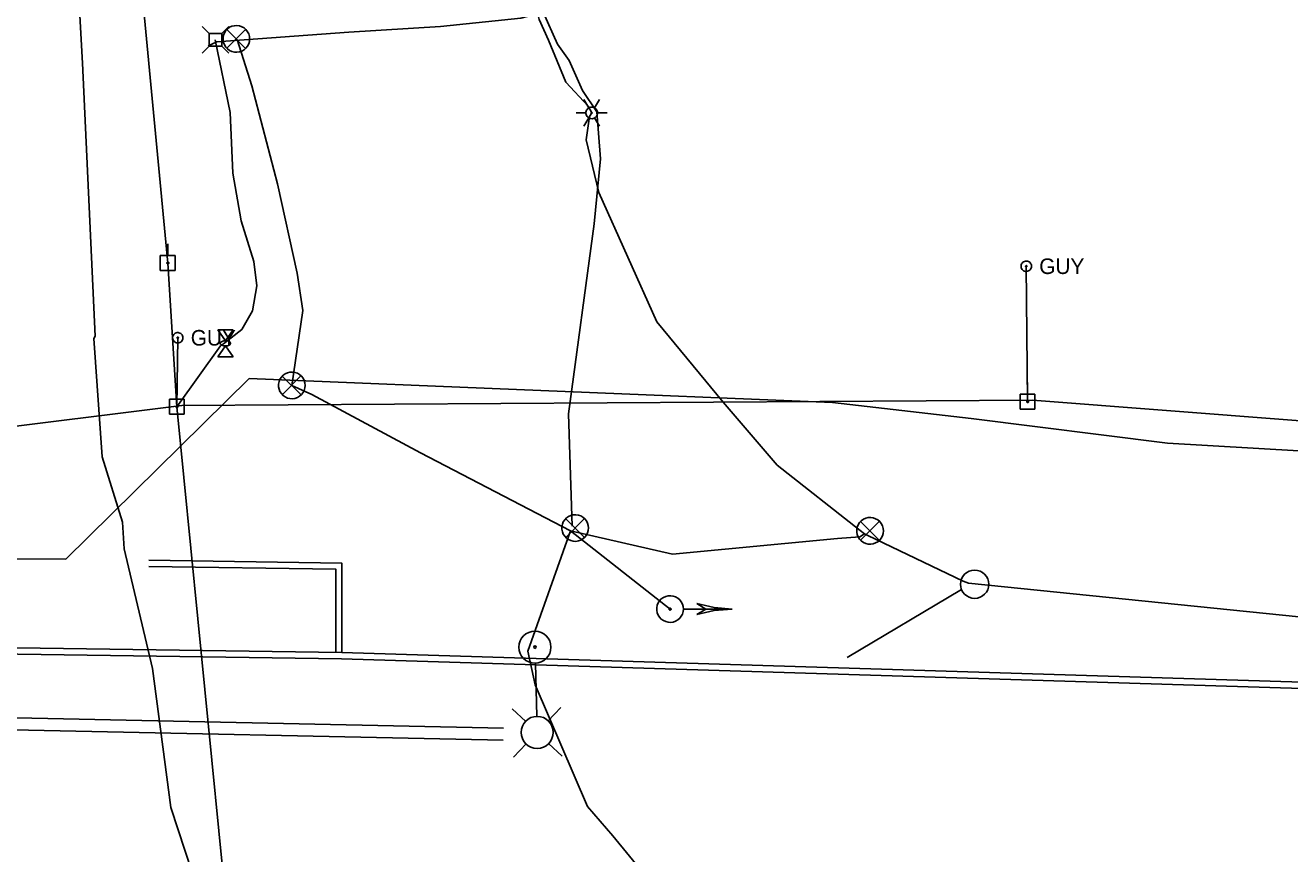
# Model space of a CAD drawing. Extents: x 596028 to 606371, y 330010 to 403088.
# Drawn here: x 603448.5 to 603761.1, y 349941 to 350145.8 of the extents above; entities that cross this region are included whole.
import ezdxf

# ---------------------------------------------------------------- set-up
doc = ezdxf.new("R2010")
doc.units = 0
for name, color, linetype in [('E_FTMS', 7, 'Continuous'), ('E_FTMS_Conduit', 7, 'Continuous'), ('E_LTG', 7, 'Continuous'), ('E_LTG_CID', 7, 'Continuous'), ('E_UTL_E', 7, 'Continuous'), ('E_UTL_E_Bold', 7, 'Continuous'), ('E_UTL_E_UG', 7, 'Continuous'), ('E_UTL_EGuyWire', 7, 'Continuous'), ('E_UTL_EPowerPole', 7, 'Continuous'), ('E_UTL_FO_UG_QWEST', 7, 'Continuous'), ('E_UTL_G_UG', 7, 'Continuous'), ('E_UTL_Overhead', 7, 'Continuous'), ('E_UTL_T_UG', 7, 'Continuous')]:
    doc.layers.add(name, color=color, linetype=linetype)

msp = doc.modelspace()

# ---------------------------------------------------------------- linework, layer by layer
at = {"layer": 'E_FTMS'}
msp.add_line((603679.91, 350006.37), (603651.7, 349989.5), dxfattribs=at)
for points in [[(603503.94, 350142.46), (603503.88, 350143.08), (603503.71, 350143.68), (603503.42, 350144.24), (603503.03, 350144.74), (603502.56, 350145.15), (603502.01, 350145.46), (603501.42, 350145.66), (603500.8, 350145.75), (603500.17, 350145.72), (603499.56, 350145.58), (603498.99, 350145.32), (603498.48, 350144.95), (603498.05, 350144.5), (603497.71, 350143.97), (603497.48, 350143.39), (603497.36, 350142.77), (603497.36, 350142.14), (603497.48, 350141.53), (603497.71, 350140.95), (603498.05, 350140.42), (603498.48, 350139.96), (603498.99, 350139.6), (603499.56, 350139.34), (603500.17, 350139.19), (603500.8, 350139.16), (603501.42, 350139.25), (603502.01, 350139.46), (603502.56, 350139.77), (603503.03, 350140.18), (603503.42, 350140.67), (603503.71, 350141.23), (603503.88, 350141.83), (603503.94, 350142.46)], [(603502.91, 350144.79), (603498.3, 350140.14)], [(603498.3, 350144.74), (603502.95, 350140.09)], [(603517.67, 350056.79), (603517.61, 350057.41), (603517.43, 350058.01), (603517.15, 350058.57), (603516.76, 350059.07), (603516.28, 350059.48), (603515.74, 350059.79), (603515.15, 350060), (603514.53, 350060.08), (603513.9, 350060.05), (603513.29, 350059.91), (603512.72, 350059.65), (603512.21, 350059.28), (603511.78, 350058.83), (603511.44, 350058.3), (603511.2, 350057.72), (603511.09, 350057.1), (603511.09, 350056.47), (603511.2, 350055.86), (603511.44, 350055.28), (603511.78, 350054.75), (603512.21, 350054.29), (603512.72, 350053.93), (603513.29, 350053.67), (603513.9, 350053.52), (603514.53, 350053.49), (603515.15, 350053.58), (603515.74, 350053.79), (603516.28, 350054.1), (603516.76, 350054.51), (603517.15, 350055), (603517.43, 350055.56), (603517.61, 350056.16), (603517.67, 350056.79)], [(603516.63, 350059.12), (603512.02, 350054.47)], [(603512.02, 350059.08), (603516.68, 350054.42)], [(603587.73, 350021.54), (603587.67, 350022.16), (603587.49, 350022.76), (603587.2, 350023.32), (603586.82, 350023.81), (603586.34, 350024.23), (603585.8, 350024.54), (603585.21, 350024.74), (603584.58, 350024.83), (603583.96, 350024.8), (603583.35, 350024.66), (603582.78, 350024.4), (603582.27, 350024.03), (603581.83, 350023.58), (603581.49, 350023.05), (603581.26, 350022.47), (603581.14, 350021.85), (603581.14, 350021.22), (603581.26, 350020.61), (603581.49, 350020.03), (603581.83, 350019.5), (603582.27, 350019.04), (603582.78, 350018.68), (603583.35, 350018.42), (603583.96, 350018.27), (603584.58, 350018.24), (603585.21, 350018.33), (603585.8, 350018.54), (603586.34, 350018.85), (603586.82, 350019.26), (603587.2, 350019.75), (603587.49, 350020.31), (603587.67, 350020.91), (603587.73, 350021.54)], [(603586.69, 350023.87), (603582.08, 350019.21)], [(603582.08, 350023.82), (603586.73, 350019.17)], [(603660.63, 350020.83), (603660.57, 350021.45), (603660.39, 350022.06), (603660.1, 350022.61), (603659.71, 350023.11), (603659.24, 350023.52), (603658.7, 350023.83), (603658.1, 350024.04), (603657.48, 350024.13), (603656.86, 350024.1), (603656.25, 350023.95), (603655.68, 350023.69), (603655.16, 350023.32), (603654.73, 350022.87), (603654.39, 350022.34), (603654.16, 350021.76), (603654.04, 350021.14), (603654.04, 350020.52), (603654.16, 350019.9), (603654.39, 350019.32), (603654.73, 350018.79), (603655.16, 350018.34), (603655.68, 350017.97), (603656.25, 350017.71), (603656.86, 350017.56), (603657.48, 350017.53), (603658.1, 350017.62), (603658.7, 350017.83), (603659.24, 350018.14), (603659.71, 350018.55), (603660.1, 350019.05), (603660.39, 350019.6), (603660.57, 350020.21), (603660.63, 350020.83)], [(603659.59, 350023.16), (603654.98, 350018.51)], [(603654.98, 350023.12), (603659.63, 350018.46)], [(603611.17, 350001.5), (603611.11, 350002.13), (603610.94, 350002.73), (603610.65, 350003.28), (603610.26, 350003.78), (603609.79, 350004.19), (603609.25, 350004.5), (603608.65, 350004.71), (603608.03, 350004.8), (603607.4, 350004.77), (603606.8, 350004.62), (603606.22, 350004.36), (603605.71, 350003.99), (603605.28, 350003.54), (603604.94, 350003.01), (603604.71, 350002.43), (603604.59, 350001.81), (603604.59, 350001.19), (603604.71, 350000.57), (603604.94, 349999.99), (603605.28, 349999.46), (603605.71, 349999.01), (603606.22, 349998.64), (603606.8, 349998.38), (603607.4, 349998.23), (603608.03, 349998.2), (603608.65, 349998.29), (603609.25, 349998.5), (603609.79, 349998.81), (603610.26, 349999.22), (603610.65, 349999.72), (603610.94, 350000.27), (603611.11, 350000.88), (603611.17, 350001.5)], [(603608.13, 350001.5), (603608.12, 350001.55), (603608.11, 350001.59), (603608.09, 350001.64), (603608.06, 350001.67), (603608.02, 350001.71), (603607.98, 350001.73), (603607.93, 350001.75), (603607.89, 350001.75), (603607.84, 350001.75), (603607.79, 350001.74), (603607.75, 350001.72), (603607.71, 350001.69), (603607.68, 350001.66), (603607.65, 350001.62), (603607.63, 350001.57), (603607.62, 350001.52), (603607.62, 350001.48), (603607.63, 350001.43), (603607.65, 350001.38), (603607.68, 350001.34), (603607.71, 350001.31), (603607.75, 350001.28), (603607.79, 350001.26), (603607.84, 350001.25), (603607.89, 350001.25), (603607.93, 350001.26), (603607.98, 350001.27), (603608.02, 350001.29), (603608.06, 350001.33), (603608.09, 350001.36), (603608.11, 350001.41), (603608.12, 350001.45), (603608.13, 350001.5)], [(603623.27, 350001.5), (603611.23, 350001.5)], [(603623.27, 350001.5), (603618.82, 350001.85), (603614.47, 350002.88)], [(603616.68, 350001.5), (603614.47, 350002.88)], [(603623.27, 350001.5), (603618.82, 350001.15), (603614.47, 350000.13)], [(603614.47, 350000.13), (603616.68, 350001.5)]]:
    msp.add_lwpolyline(points, dxfattribs=at)
msp.add_circle((603683.17, 350007.63), 3.5, dxfattribs=at)
at = {"layer": 'E_FTMS_Conduit'}
for points in [[(603550.11, 350285.52), (603561.99, 350249.22), (603565.86, 350218.8), (603571.07, 350187.75), (603575.18, 350163.49), (603576.5, 350149.08), (603580.05, 350141.16), (603582.94, 350137.08), (603586.21, 350129.73), (603589.8, 350124.4), (603590.67, 350112.8), (603589.13, 350096.71), (603582.8, 350049.8), (603583.68, 350022)], [(603493.66, 350140.75), (603495.84, 350141.7), (603528.48, 350144.11), (603551.14, 350145.54), (603570.99, 350147.6), (603573.77, 350148.28), (603575.19, 350148.59)], [(603514.37, 350056.79), (603517.13, 350075.28), (603515.66, 350084.52), (603510.83, 350106.62), (603504.46, 350130.87), (603500.87, 350142.28)], [(603514.37, 350056.79), (603519.33, 350054.54), (603546.19, 350040.11), (603583.24, 350020.86)], [(603583.24, 350020.86), (603607.87, 350001.5)], [(603583.24, 350020.86), (603608.49, 350015.05), (603649.23, 350018.98), (603654.78, 350019.38), (603655.98, 350020.11), (603656.75, 350019.7), (603680.35, 350008.39), (603681.64, 350007.87)]]:
    msp.add_lwpolyline(points, dxfattribs=at)
at = {"layer": 'E_LTG'}
for points in [[(603587.8, 350125.4), (603586.6, 350127.46)], [(603589.22, 350125.4), (603590.42, 350127.46)], [(603584.7, 350124.16), (603587.08, 350124.16)], [(603589.94, 350124.16), (603589.91, 350124.43), (603589.84, 350124.69), (603589.71, 350124.93), (603589.54, 350125.15), (603589.34, 350125.32), (603589.1, 350125.46), (603588.85, 350125.55), (603588.58, 350125.59), (603588.31, 350125.57), (603588.04, 350125.51), (603587.8, 350125.4), (603587.57, 350125.24), (603587.39, 350125.04), (603587.24, 350124.81), (603587.14, 350124.56), (603587.09, 350124.3), (603587.09, 350124.02), (603587.14, 350123.76), (603587.24, 350123.5), (603587.39, 350123.28), (603587.57, 350123.08), (603587.8, 350122.92), (603588.04, 350122.81), (603588.31, 350122.75), (603588.58, 350122.73), (603588.85, 350122.77), (603589.1, 350122.86), (603589.34, 350123), (603589.54, 350123.17), (603589.71, 350123.39), (603589.84, 350123.63), (603589.91, 350123.89), (603589.94, 350124.16)], [(603589.94, 350124.16), (603589.91, 350124.43), (603589.84, 350124.69), (603589.71, 350124.93), (603589.54, 350125.15), (603589.34, 350125.32), (603589.1, 350125.46), (603588.85, 350125.55), (603588.58, 350125.59), (603588.31, 350125.57), (603588.04, 350125.51), (603587.8, 350125.4), (603587.57, 350125.24), (603587.39, 350125.04), (603587.24, 350124.81), (603587.14, 350124.56), (603587.09, 350124.3), (603587.09, 350124.02), (603587.14, 350123.76), (603587.24, 350123.5), (603587.39, 350123.28), (603587.57, 350123.08), (603587.8, 350122.92), (603588.04, 350122.81), (603588.31, 350122.75), (603588.58, 350122.73), (603588.85, 350122.77), (603589.1, 350122.86), (603589.34, 350123), (603589.54, 350123.17), (603589.71, 350123.39), (603589.84, 350123.63), (603589.91, 350123.89), (603589.94, 350124.16)], [(603589.94, 350124.16), (603589.91, 350124.43), (603589.84, 350124.69), (603589.71, 350124.93), (603589.54, 350125.15), (603589.34, 350125.32), (603589.1, 350125.46), (603588.85, 350125.55), (603588.58, 350125.59), (603588.31, 350125.57), (603588.04, 350125.51), (603587.8, 350125.4), (603587.57, 350125.24), (603587.39, 350125.04), (603587.24, 350124.81), (603587.14, 350124.56), (603587.09, 350124.3), (603587.09, 350124.02), (603587.14, 350123.76), (603587.24, 350123.5), (603587.39, 350123.28), (603587.57, 350123.08), (603587.8, 350122.92), (603588.04, 350122.81), (603588.31, 350122.75), (603588.58, 350122.73), (603588.85, 350122.77), (603589.1, 350122.86), (603589.34, 350123), (603589.54, 350123.17), (603589.71, 350123.39), (603589.84, 350123.63), (603589.91, 350123.89), (603589.94, 350124.16)], [(603588.63, 350124.16), (603588.63, 350124.18), (603588.62, 350124.2), (603588.61, 350124.22), (603588.6, 350124.24), (603588.58, 350124.26), (603588.56, 350124.27), (603588.54, 350124.28), (603588.52, 350124.28), (603588.49, 350124.28), (603588.47, 350124.27), (603588.45, 350124.26), (603588.43, 350124.25), (603588.42, 350124.23), (603588.4, 350124.21), (603588.4, 350124.19), (603588.39, 350124.17), (603588.39, 350124.15), (603588.4, 350124.13), (603588.4, 350124.11), (603588.42, 350124.09), (603588.43, 350124.07), (603588.45, 350124.06), (603588.47, 350124.05), (603588.49, 350124.04), (603588.52, 350124.04), (603588.54, 350124.04), (603588.56, 350124.05), (603588.58, 350124.06), (603588.6, 350124.08), (603588.61, 350124.1), (603588.62, 350124.12), (603588.63, 350124.14), (603588.63, 350124.16)], [(603589.94, 350124.16), (603592.32, 350124.16)], [(603586.6, 350120.86), (603587.8, 350122.92)], [(603590.42, 350120.86), (603589.22, 350122.92)], [(603574.91, 349975.02), (603574.57, 349988.06)], [(603572.18, 349973.69), (603568.87, 349976.84)], [(603577.72, 349973.83), (603580.86, 349977.15)], [(603572.33, 349968.15), (603569.18, 349964.84)], [(603577.86, 349968.3), (603581.17, 349965.15)]]:
    msp.add_lwpolyline(points, dxfattribs=at)
for centre, radius in [((603574.47, 349992.09), 3.96), ((603574.47, 349992.09), 0.303), ((603575.02, 349971), 3.96)]:
    msp.add_circle(centre, radius, dxfattribs=at)
at = {"layer": 'E_LTG_CID'}
msp.add_line((603681.64, 350007.87), (603786.08, 349997.29), dxfattribs=at)
for points in [[(603575.2, 350148.58), (603575.49, 350147.29), (603577.82, 350142.15), (603582.07, 350131.77), (603587.61, 350125.84), (603588.51, 350124.16), (603587.98, 350123.3), (603587.16, 350117.48), (603590.23, 350104.45), (603604.63, 350072.51), (603620.98, 350052.63), (603634.38, 350037.03), (603654.88, 350020.9), (603655.98, 350020.11)], [(603572.73, 349991.09), (603583.24, 350020.86)], [(603621.26, 349910.44), (603620.8, 349911.86), (603616.21, 349917.99), (603593.76, 349945.42), (603587.47, 349952.66), (603574.53, 349982.77), (603572.73, 349991.09)]]:
    msp.add_lwpolyline(points, dxfattribs=at)
at = {"layer": 'E_UTL_E'}
for points in [[(603493.97, 350143.75), (603492.21, 350145.5)], [(603497.06, 350143.75), (603498.81, 350145.5)], [(603497.06, 350143.75), (603493.97, 350143.75)], [(603493.97, 350143.75), (603493.97, 350140.66)], [(603497.06, 350140.66), (603497.06, 350143.75)], [(603493.97, 350140.66), (603492.21, 350138.9)], [(603493.97, 350140.66), (603497.06, 350140.66)], [(603497.06, 350140.66), (603498.81, 350138.9)]]:
    msp.add_lwpolyline(points, dxfattribs=at)
at = {"layer": 'E_UTL_E_Bold'}
for points in [[(603496.05, 350070.49), (603499.86, 350070.49)], [(603497.95, 350067.83), (603496.05, 350070.49)], [(603499.86, 350070.49), (603497.95, 350067.83)], [(603499.22, 350067.19), (603499.2, 350067.31), (603499.13, 350067.43), (603499.02, 350067.54), (603498.87, 350067.63), (603498.69, 350067.71), (603498.48, 350067.77), (603498.25, 350067.81), (603498.01, 350067.83), (603497.77, 350067.82), (603497.54, 350067.79), (603497.32, 350067.74), (603497.12, 350067.67), (603496.96, 350067.58), (603496.82, 350067.48), (603496.74, 350067.37), (603496.69, 350067.25), (603496.69, 350067.13), (603496.74, 350067.01), (603496.82, 350066.9), (603496.96, 350066.8), (603497.12, 350066.71), (603497.32, 350066.64), (603497.54, 350066.59), (603497.77, 350066.56), (603498.01, 350066.56), (603498.25, 350066.57), (603498.48, 350066.61), (603498.69, 350066.67), (603498.87, 350066.75), (603499.02, 350066.85), (603499.13, 350066.96), (603499.2, 350067.07), (603499.22, 350067.19)], [(603497.95, 350066.56), (603496.05, 350063.89)], [(603496.05, 350063.89), (603499.86, 350063.89)], [(603499.86, 350063.89), (603497.95, 350066.56)]]:
    msp.add_lwpolyline(points, dxfattribs=at)
at = {"layer": 'E_UTL_E_UG'}
msp.add_lwpolyline([(603485.97, 350051.51), (603496.71, 350066.56), (603497.45, 350067.05), (603502.05, 350070.65), (603504.61, 350075.23), (603505.7, 350081.37), (603504.98, 350087.44), (603501.88, 350097.49), (603499.75, 350109.27), (603499.11, 350124.26), (603495.41, 350142.26)], dxfattribs=at)
at = {"layer": 'E_UTL_EGuyWire'}
for p, q in [((603695.93, 350086.25), (603696.28, 350052.77)), ((603486.17, 350068.57), (603485.97, 350051.51))]:
    msp.add_line(p, q, dxfattribs=at)
for points in [[(603697.21, 350086.25), (603697.19, 350086.49), (603697.12, 350086.73), (603697.01, 350086.94), (603696.86, 350087.14), (603696.67, 350087.3), (603696.46, 350087.42), (603696.23, 350087.5), (603695.99, 350087.53), (603695.75, 350087.52), (603695.51, 350087.46), (603695.29, 350087.36), (603695.09, 350087.22), (603694.92, 350087.04), (603694.79, 350086.84), (603694.7, 350086.61), (603694.65, 350086.37), (603694.65, 350086.13), (603694.7, 350085.89), (603694.79, 350085.66), (603694.92, 350085.46), (603695.09, 350085.28), (603695.29, 350085.14), (603695.51, 350085.04), (603695.75, 350084.98), (603695.99, 350084.97), (603696.23, 350085), (603696.46, 350085.08), (603696.67, 350085.2), (603696.86, 350085.36), (603697.01, 350085.56), (603697.12, 350085.77), (603697.19, 350086.01), (603697.21, 350086.25)], [(603696.09, 350086.25), (603696.09, 350086.28), (603696.08, 350086.31), (603696.06, 350086.34), (603696.05, 350086.36), (603696.02, 350086.38), (603696, 350086.4), (603695.97, 350086.41), (603695.94, 350086.41), (603695.91, 350086.41), (603695.88, 350086.4), (603695.85, 350086.39), (603695.82, 350086.37), (603695.8, 350086.35), (603695.79, 350086.32), (603695.78, 350086.3), (603695.77, 350086.27), (603695.77, 350086.23), (603695.78, 350086.2), (603695.79, 350086.18), (603695.8, 350086.15), (603695.82, 350086.13), (603695.85, 350086.11), (603695.88, 350086.1), (603695.91, 350086.09), (603695.94, 350086.09), (603695.97, 350086.09), (603696, 350086.1), (603696.02, 350086.12), (603696.05, 350086.14), (603696.06, 350086.16), (603696.08, 350086.19), (603696.09, 350086.22), (603696.09, 350086.25)], [(603487.45, 350068.57), (603487.43, 350068.81), (603487.36, 350069.04), (603487.25, 350069.26), (603487.1, 350069.45), (603486.91, 350069.61), (603486.7, 350069.73), (603486.47, 350069.81), (603486.23, 350069.85), (603485.99, 350069.84), (603485.75, 350069.78), (603485.53, 350069.68), (603485.33, 350069.54), (603485.16, 350069.36), (603485.03, 350069.15), (603484.94, 350068.93), (603484.89, 350068.69), (603484.89, 350068.44), (603484.94, 350068.2), (603485.03, 350067.98), (603485.16, 350067.77), (603485.33, 350067.6), (603485.53, 350067.45), (603485.75, 350067.35), (603485.99, 350067.3), (603486.23, 350067.28), (603486.47, 350067.32), (603486.7, 350067.4), (603486.91, 350067.52), (603487.1, 350067.68), (603487.25, 350067.87), (603487.36, 350068.09), (603487.43, 350068.32), (603487.45, 350068.57)], [(603486.33, 350068.57), (603486.33, 350068.6), (603486.32, 350068.63), (603486.3, 350068.65), (603486.29, 350068.68), (603486.26, 350068.7), (603486.24, 350068.71), (603486.21, 350068.72), (603486.18, 350068.73), (603486.15, 350068.72), (603486.12, 350068.72), (603486.09, 350068.7), (603486.06, 350068.69), (603486.04, 350068.67), (603486.03, 350068.64), (603486.02, 350068.61), (603486.01, 350068.58), (603486.01, 350068.55), (603486.02, 350068.52), (603486.03, 350068.49), (603486.04, 350068.47), (603486.06, 350068.44), (603486.09, 350068.43), (603486.12, 350068.41), (603486.15, 350068.41), (603486.18, 350068.41), (603486.21, 350068.41), (603486.24, 350068.42), (603486.26, 350068.44), (603486.29, 350068.46), (603486.3, 350068.48), (603486.32, 350068.51), (603486.33, 350068.54), (603486.33, 350068.57)]]:
    msp.add_lwpolyline(points, dxfattribs=at)
at = {"layer": 'E_UTL_EPowerPole'}
for points in [[(603483.7, 350088.89), (603483.7, 350091.8)], [(603485.54, 350088.89), (603481.86, 350088.89)], [(603481.86, 350088.89), (603481.86, 350085.2)], [(603485.54, 350085.2), (603485.54, 350088.89)], [(603483.97, 350087.05), (603483.97, 350087.09), (603483.95, 350087.14), (603483.93, 350087.18), (603483.9, 350087.21), (603483.87, 350087.24), (603483.83, 350087.27), (603483.79, 350087.28), (603483.74, 350087.29), (603483.7, 350087.29), (603483.65, 350087.27), (603483.61, 350087.26), (603483.58, 350087.23), (603483.54, 350087.2), (603483.52, 350087.16), (603483.5, 350087.12), (603483.49, 350087.07), (603483.49, 350087.03), (603483.5, 350086.98), (603483.52, 350086.94), (603483.54, 350086.9), (603483.58, 350086.87), (603483.61, 350086.84), (603483.65, 350086.82), (603483.7, 350086.81), (603483.74, 350086.81), (603483.79, 350086.82), (603483.83, 350086.83), (603483.87, 350086.85), (603483.9, 350086.88), (603483.93, 350086.92), (603483.95, 350086.96), (603483.97, 350087), (603483.97, 350087.05)], [(603481.86, 350085.2), (603485.54, 350085.2)], [(603696.24, 350054.62), (603696.24, 350057.53)], [(603485.94, 350053.35), (603485.94, 350056.26)], [(603698.09, 350054.62), (603694.4, 350054.62)], [(603694.4, 350054.62), (603694.4, 350050.93)], [(603698.09, 350050.93), (603698.09, 350054.62)], [(603487.78, 350053.35), (603484.09, 350053.35)], [(603484.09, 350053.35), (603484.09, 350049.66)], [(603486.21, 350051.51), (603486.2, 350051.56), (603486.19, 350051.6), (603486.17, 350051.64), (603486.14, 350051.68), (603486.11, 350051.71), (603486.07, 350051.73), (603486.03, 350051.74), (603485.98, 350051.75), (603485.94, 350051.75), (603485.89, 350051.74), (603485.85, 350051.72), (603485.81, 350051.69), (603485.78, 350051.66), (603485.76, 350051.62), (603485.74, 350051.58), (603485.73, 350051.53), (603485.73, 350051.49), (603485.74, 350051.44), (603485.76, 350051.4), (603485.78, 350051.36), (603485.81, 350051.33), (603485.85, 350051.31), (603485.89, 350051.29), (603485.94, 350051.28), (603485.98, 350051.27), (603486.03, 350051.28), (603486.07, 350051.3), (603486.11, 350051.32), (603486.14, 350051.35), (603486.17, 350051.38), (603486.19, 350051.42), (603486.2, 350051.47), (603486.21, 350051.51)], [(603487.78, 350049.66), (603487.78, 350053.35)], [(603696.52, 350052.77), (603696.51, 350052.82), (603696.5, 350052.86), (603696.48, 350052.9), (603696.45, 350052.94), (603696.42, 350052.97), (603696.38, 350052.99), (603696.33, 350053.01), (603696.29, 350053.01), (603696.24, 350053.01), (603696.2, 350053), (603696.16, 350052.98), (603696.12, 350052.95), (603696.09, 350052.92), (603696.06, 350052.88), (603696.05, 350052.84), (603696.04, 350052.8), (603696.04, 350052.75), (603696.05, 350052.71), (603696.06, 350052.66), (603696.09, 350052.63), (603696.12, 350052.59), (603696.16, 350052.57), (603696.2, 350052.55), (603696.24, 350052.54), (603696.29, 350052.54), (603696.33, 350052.54), (603696.38, 350052.56), (603696.42, 350052.58), (603696.45, 350052.61), (603696.48, 350052.65), (603696.5, 350052.69), (603696.51, 350052.73), (603696.52, 350052.77)], [(603484.09, 350049.66), (603487.78, 350049.66)], [(603694.4, 350050.93), (603698.09, 350050.93)]]:
    msp.add_lwpolyline(points, dxfattribs=at)
at = {"layer": 'E_UTL_FO_UG_QWEST'}
msp.add_lwpolyline([(603500.08, 349904.76), (603484.43, 349952.42), (603479.94, 349986.84), (603472.93, 350016.37), (603472.53, 350022.97), (603467.48, 350039.11), (603465.43, 350068.42), (603465.78, 350068.99), (603462.63, 350136.46), (603460.06, 350182.47), (603456.92, 350234.22), (603462.57, 350276.57), (603464.06, 350325.25), (603464.23, 350373.72), (603456.32, 350421.92), (603453.14, 350468.35), (603457.26, 350519.89), (603458.06, 350580.31)], dxfattribs=at)
at = {"layer": 'E_UTL_G_UG'}
for points in [[(603247.07, 350019.95), (603318.24, 350017.66), (603336.79, 350016.35), (603384.58, 350014.07), (603430.96, 350013.96), (603458.52, 350013.84), (603503.86, 350058.46), (603648.07, 350052.57), (603682.34, 350048.59), (603730.88, 350042.54), (603763.3, 350040.62), (603792.31, 350038.87), (603814.03, 350037.15), (603835.65, 350036.86), (603952.18, 350026.33), (603985.15, 350025.13), (604017.27, 350023.85), (604050.12, 350022.04), (604102.3, 350017.06), (604148.94, 350012.3), (604207.72, 350003.02), (604224.15, 350001.18), (604252.85, 349997.07), (604335.69, 349990.44)], [(603479.03, 350012.05), (603525.22, 350011.4), (603525.22, 349990.73)], [(603479.05, 350013.55), (603526.72, 350012.88), (603526.72, 349990.73)], [(602826.88, 349975.76), (603315.77, 349969.2), (603332.35, 349992.01), (603526.69, 349989.23), (604482.02, 349959.73)], [(602826.9, 349977.26), (603315.02, 349970.71), (603331.6, 349993.52), (603526.72, 349990.73), (604482.07, 349961.23)]]:
    msp.add_lwpolyline(points, dxfattribs=at)
at = {"layer": 'E_UTL_Overhead'}
msp.add_line((603483.73, 350087.05), (603468.46, 350246.59), dxfattribs=at)
for points in [[(603501.53, 349894.25), (603485.97, 350051.51), (603483.73, 350087.05)], [(603181.28, 350035.1), (603329.32, 350032.13), (603487.19, 350051.84), (603697.5, 350053.11), (603794.73, 350045.64), (603986.8, 350030.72), (604135.55, 350019.1), (604355.8, 350001.36), (604456.04, 349993.24), (604557.11, 349986.14), (604654.49, 349982.64), (604747.33, 349981.14), (604855.96, 349980.06), (604969.76, 349979.4), (605156.33, 349975.18)]]:
    msp.add_lwpolyline(points, dxfattribs=at)
at = {"layer": 'E_UTL_T_UG'}
msp.add_line((602560.12, 349990.4), (603566.6, 349969.05), dxfattribs=at)
msp.add_lwpolyline([(602560.18, 349993.4), (603566.67, 349972.04)], dxfattribs=at)

# ---------------------------------------------------------------- texts
at = {"layer": 'E_UTL_EGuyWire'}
for p in [(603699.14, 350084.33), (603489.38, 350066.64)]:
    msp.add_text('GUY', height=3.85, dxfattribs=at).set_placement(p)

doc.saveas('drawing.dxf')
